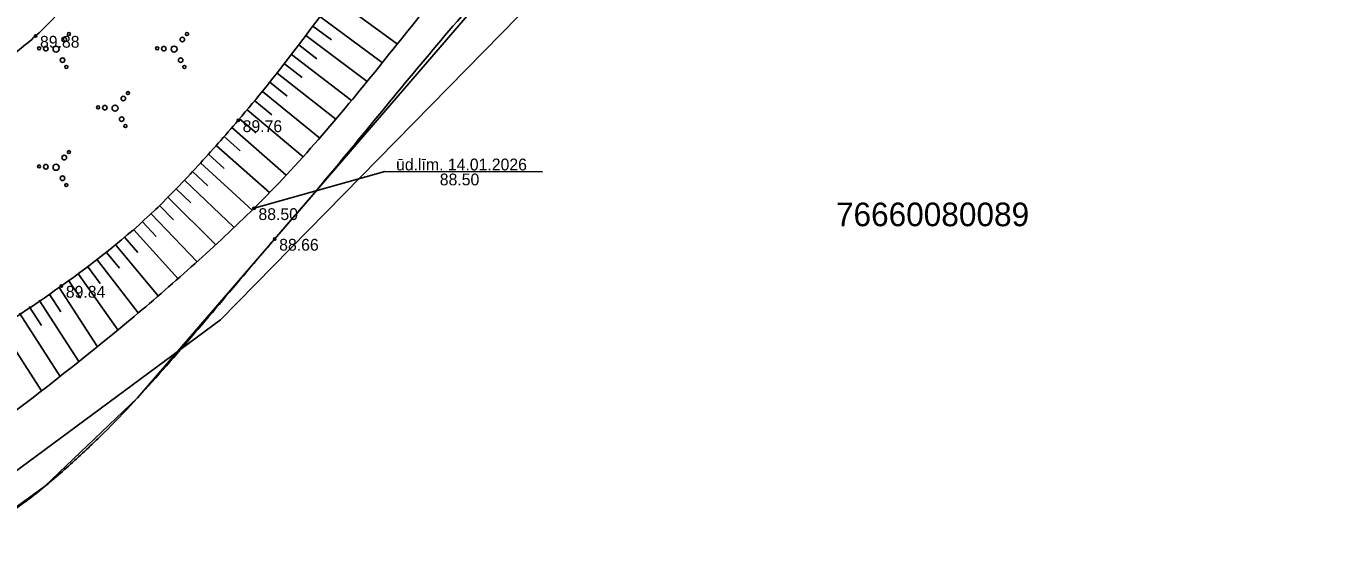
# Model space of a CAD drawing. Extents: x 635228 to 635525, y 248590 to 248800.
# Drawn here: x 635431.2 to 635486.1, y 248671.4 to 248693.5 of the extents above; entities that cross this region are included whole.
import ezdxf

# ---------------------------------------------------------------- set-up
doc = ezdxf.new("R2010")
doc.units = 0
for name, color, linetype in [('HIDG_GRAV_####_####_#', 7, 'Continuous'), ('HIDG_GRAV_####_TKST_#', 7, 'Continuous'), ('HIDG_PLIN_####_####_#', 7, 'Continuous'), ('RAMI_UZMR_####_####_#', 7, 'Continuous'), ('RELJ_AATZ_####_TKST_#', 7, 'Continuous'), ('RELJ_ELEM_####_####_#', 7, 'Continuous'), ('RELJ_HORZ_RESN_####_#', 7, 'Continuous'), ('RELJ_NOGA_####_####_#', 7, 'Continuous'), ('ROBZ_IERR_####_####_#', 7, 'Continuous'), ('ROBZ_IERR_####_TKST_#', 7, 'Continuous'), ('ROBZ_UZMR_####_####_#', 7, 'Continuous'), ('TERT_ELEM_####_####_#', 7, 'Continuous'), ('TERT_KONT_####_####_#', 7, 'Continuous')]:
    doc.layers.add(name, color=color, linetype=linetype)

msp = doc.modelspace()

# ---------------------------------------------------------------- linework, layer by layer
at = {"layer": 'HIDG_GRAV_####_####_#'}
for points in [[(635394.244, 248623.295), (635394.9074355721, 248630.6631552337), (635396.5650242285, 248636.944974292), (635397.8888882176, 248639.97580624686), (635399.2686043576, 248642.98780740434), (635400.0423829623, 248644.69884236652), (635400.835233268, 248646.3905777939), (635402.4795660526, 248649.72803076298), (635404.20443685, 248653.0239277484), (635406.0126797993, 248656.30203018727), (635407.0670223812, 248658.14081276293), (635408.1930324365, 248659.92698593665), (635409.4621962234, 248661.60192368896), (635410.172800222, 248662.37935865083), (635410.946, 248663.10700000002), (635413.0008032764, 248664.6744257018), (635415.1640977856, 248666.05372522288), (635417.3478434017, 248667.38916213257), (635419.464, 248668.825), (635422.2083511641, 248670.85354035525), (635424.965867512, 248672.86854694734), (635430.4558647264, 248676.93578902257), (635435.8049295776, 248681.1823865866), (635438.3862804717, 248683.4215875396), (635439.6466024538, 248684.57867623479), (635440.8840000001, 248685.76400000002), (635443.6087249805, 248688.6747140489), (635446.1599310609, 248691.73220612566), (635448.6719216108, 248694.81834513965), (635451.279, 248697.815), (635453.9336502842, 248700.48189136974), (635456.6811388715, 248703.07136968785), (635459.3523080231, 248705.7266631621), (635461.7780000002, 248708.59100000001), (635461.778, 248708.59100000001)], [(635396.7397638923, 248625.2320466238), (635397.9986579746, 248634.27312358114), (635398.9188026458, 248636.96227546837), (635399.5920874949, 248638.24717771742), (635399.9292604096, 248638.88899780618), (635400.2466831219, 248639.53584001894), (635401.591165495, 248642.41958219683), (635402.9524948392, 248645.2868638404), (635405.8217854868, 248650.96088254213), (635407.5583128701, 248653.91205967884), (635409.4799859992, 248656.7354955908), (635411.5283407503, 248659.48290512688), (635413.6449129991, 248662.20600313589), (635414.8182615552, 248663.6538935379), (635415.4704678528, 248664.3057478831), (635416.2076616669, 248664.85985159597), (635417.1601741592, 248665.41138033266), (635418.1313630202, 248665.91742947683), (635419.1067857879, 248666.41122678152), (635420.072, 248666.926), (635421.5645353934, 248667.7418115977), (635423.0692260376, 248668.5354410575), (635426.0762392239, 248670.12612318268), (635429.0153718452, 248671.8379856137), (635430.4352117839, 248672.78309045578), (635431.128452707, 248673.2855892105), (635431.8089561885, 248673.81096758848), (635433.1953696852, 248675.0040709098), (635434.526751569, 248676.2563297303), (635437.0226234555, 248678.92292892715), (635441.762, 248684.467), (635443.1273679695, 248686.0473501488), (635444.4678763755, 248687.6485508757), (635447.1219662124, 248690.87245996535), (635449.819572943, 248694.05663907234), (635451.2144774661, 248695.60817732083), (635452.6560000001, 248697.119), (635458.0231966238, 248702.2419696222), (635463.584, 248707.15000000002)]]:
    msp.add_spline(points, degree=3, dxfattribs=at)
at = {"layer": 'HIDG_PLIN_####_####_#'}
msp.add_lwpolyline([(635440.8840000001, 248685.76400000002), (635446.4215187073, 248687.31237986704), (635453.0919673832, 248687.30254225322)], dxfattribs=at)
at = {"layer": 'RAMI_UZMR_####_####_#'}
msp.add_lwpolyline([(635426.003, 248728.15499999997), (635436.69, 248722.584), (635450.108, 248715.45700000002), (635458.287, 248711.34600000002), (635461.7780000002, 248708.59100000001), (635463.584, 248707.15000000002), (635452.6560000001, 248697.119), (635441.762, 248684.467), (635435.9528772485, 248677.73413872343), (635432.018527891, 248673.97985762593), (635429.363741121, 248672.06248825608), (635427.0556775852, 248670.66460585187), (635420.072, 248666.926), (635415.05332695, 248664.00973325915), (635408.095218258, 248654.65947737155), (635398.6701763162, 248636.43948679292), (635398.046283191, 248634.41686083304), (635396.3166782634, 248622.87374513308), (635394.244, 248623.295), (635390.206, 248622.483), (635381.566, 248626.41900000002), (635379.918, 248627.738), (635364.657, 248634.36500000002)], dxfattribs=at)
at = {"layer": 'RELJ_ELEM_####_####_#'}
for centre in [(635431.635, 248693.06), (635440.2150000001, 248689.48700000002), (635440.8840000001, 248685.76400000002), (635441.762, 248684.467), (635432.728, 248682.47600000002)]:
    msp.add_circle(centre, 0.05, dxfattribs=at)
at = {"layer": 'RELJ_HORZ_RESN_####_#'}
msp.add_spline([(635396.8403365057, 248673.83023932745), (635398.5699520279, 248674.74721849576), (635400.1196081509, 248675.6687893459), (635401.3847631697, 248676.59316814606), (635401.8779834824, 248677.05585311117), (635402.2608753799, 248677.51857116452), (635402.5005008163, 248677.92779942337), (635402.9962003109, 248679.47940420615), (635403.1093939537, 248680.10527297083), (635403.2077718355, 248680.73304831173), (635403.3050539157, 248681.36081107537), (635403.4149601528, 248681.98664210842), (635403.9947087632, 248684.49620174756), (635404.4941894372, 248685.58182624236), (635404.822447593, 248686.0525951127), (635405.213, 248686.464), (635405.5227683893, 248686.49325254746), (635405.8948771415, 248686.27621660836), (635406.269797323, 248686.04907236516), (635406.588, 248686.048), (635407.1331532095, 248686.47133617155), (635407.6549224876, 248686.94769115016), (635408.6437981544, 248688.02779111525), (635410.511320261, 248690.47588617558), (635412.43838879, 248692.8856225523), (635414.0718482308, 248694.36296271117), (635414.672826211, 248694.7503376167), (635415.8418707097, 248695.38166460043), (635417.0157559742, 248695.99905223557), (635418.2014500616, 248696.5900310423), (635419.4059210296, 248697.14213154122), (635424.3998390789, 248699.29274669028), (635429.4588912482, 248701.50672660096), (635434.3873884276, 248704.0886148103), (635435.2434356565, 248704.60530447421), (635437.7315604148, 248706.27775516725), (635439.1970704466, 248707.5552960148), (635439.8338858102, 248708.26101524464), (635440.1227716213, 248708.63326282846), (635440.3898668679, 248709.01944554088), (635440.6922176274, 248709.6864690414), (635440.8034457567, 248710.32396866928)], degree=3, dxfattribs=at)
at = {"layer": 'RELJ_NOGA_####_####_#'}
for p, q in [((635444.2640867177, 248694.6815334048), (635446.9501521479, 248692.7079483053)), ((635443.6711792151, 248693.87626334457), (635446.3164226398, 248691.9252376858)), ((635443.3733437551, 248693.47464939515), (635444.159231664, 248692.8902927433)), ((635443.0742304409, 248693.0739865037), (635445.6670526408, 248691.12700530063)), ((635442.4707656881, 248692.2766022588), (635445.0102797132, 248690.3282610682)), ((635442.7734409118, 248692.67458055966), (635443.544555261, 248692.09194530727)), ((635442.165886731, 248691.8803093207), (635442.9197012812, 248691.29521855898)), ((635441.8583686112, 248691.48606120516), (635444.3460306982, 248689.53457838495)), ((635441.2345494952, 248690.70450682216), (635443.6628559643, 248688.73703135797)), ((635441.5480193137, 248691.09403852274), (635442.2846619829, 248690.50547088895)), ((635440.9176730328, 248690.31774175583), (635441.6351733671, 248689.7223950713)), ((635440.2724968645, 248689.55373259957), (635440.9714260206, 248688.95153464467)), ((635440.5970389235, 248689.93408666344), (635442.958460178, 248687.93922568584)), ((635439.944876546, 248689.1760233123), (635442.2476320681, 248687.16290094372)), ((635439.2844241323, 248688.42516061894), (635441.5428443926, 248686.42444521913)), ((635439.6155479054, 248688.799802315), (635440.3001597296, 248688.1974505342)), ((635438.9510520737, 248688.0525187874), (635439.6168422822, 248687.45103894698)), ((635438.276153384, 248687.31462318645), (635438.9206995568, 248686.71560371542)), ((635438.6150448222, 248687.68225136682), (635440.8048401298, 248685.6867319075)), ((635437.9339912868, 248686.95003711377), (635440.0377400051, 248684.94792143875)), ((635437.2383815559, 248686.231644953), (635439.2625636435, 248684.2212014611)), ((635437.5881101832, 248686.58897799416), (635438.2072488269, 248685.98740303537)), ((635436.8842699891, 248685.87865579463), (635437.4801655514, 248685.27329917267)), ((635436.1619816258, 248685.18711517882), (635436.7333918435, 248684.57161787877)), ((635436.5255786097, 248685.5303229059), (635438.4722431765, 248683.49912884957)), ((635435.7932493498, 248684.84943055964), (635437.6667843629, 248682.7811903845)), ((635435.0390315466, 248684.1928833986), (635436.829137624, 248682.05219983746)), ((635435.4189928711, 248684.5178794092), (635435.9683232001, 248683.88744733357)), ((635434.2609435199, 248683.5648307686), (635435.983178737, 248681.33217852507)), ((635434.6530570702, 248683.8750534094), (635435.1800791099, 248683.22053229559)), ((635433.4574724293, 248682.96962311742), (635435.1192793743, 248680.61247814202)), ((635433.8624592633, 248683.2628364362), (635434.3722396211, 248682.57773384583)), ((635432.6279048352, 248682.41137622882), (635434.2484871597, 248679.9012711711)), ((635433.0458890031, 248682.68574630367), (635433.537136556, 248681.95645475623)), ((635431.787682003, 248681.86913502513), (635433.4631615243, 248679.27084230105)), ((635432.2078449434, 248682.14017577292), (635432.7025924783, 248681.37386586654)), ((635430.9470252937, 248681.3275667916), (635432.6731329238, 248678.64622909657)), ((635431.3674439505, 248681.5982107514), (635431.8775093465, 248680.80587454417)), ((635430.1061815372, 248680.7862888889), (635431.879304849, 248678.02717532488))]:
    msp.add_line(p, q, dxfattribs=at)
msp.add_spline([(635390.206, 248622.483), (635392.6761559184, 248639.41621940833), (635395.6724652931, 248647.2597307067), (635397.9131924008, 248650.95381667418), (635399.048256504, 248652.79837067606), (635400.128, 248654.662), (635400.9493075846, 248656.2558432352), (635403.3016292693, 248661.16811378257), (635405.1862207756, 248664.14373210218), (635407.706, 248666.499), (635412.1610828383, 248669.3503906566), (635416.627, 248672.168), (635424.6828055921, 248677.31078055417), (635432.728, 248682.47600000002), (635436.7060689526, 248685.70428438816), (635438.5008534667, 248687.5575466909), (635440.2150000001, 248689.48700000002), (635442.5291182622, 248692.3528262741), (635444.7219287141, 248695.30565037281), (635446.9190248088, 248698.24939928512), (635449.246, 248701.08800000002), (635451.3600052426, 248703.48451832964), (635453.4937434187, 248705.86484004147), (635457.9500000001, 248710.44), (635458.6576193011, 248711.10744185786)], degree=3, dxfattribs=at)
at = {"layer": 'ROBZ_IERR_####_####_#'}
msp.add_lwpolyline([(635522.337313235, 248635.85405923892), (635430.9589999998, 248667.77300000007), (635424.5429999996, 248670.01400000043), (635439.4570000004, 248681.03800000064), (635465.4589999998, 248707.53900000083), (635482.5609999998, 248729.82799999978), (635498.1289999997, 248747.85500000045)], dxfattribs=at)
at = {"layer": 'ROBZ_UZMR_####_####_#'}
msp.add_lwpolyline([(635325.5420000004, 248659.74000000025), (635329.6529999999, 248676.3660000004), (635327.79, 248676.82799999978), (635337.4600999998, 248688.65990000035), (635343.3430000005, 248703.1199999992), (635360.483, 248762.61500000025), (635458.6069999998, 248711.13399999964), (635465.4589999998, 248707.53900000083), (635439.4570000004, 248681.03800000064), (635424.5429999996, 248670.01400000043), (635420.9790000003, 248667.37900000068), (635407.0700000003, 248653.17999999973), (635400.0669999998, 248641.1490000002), (635395.1619999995, 248617.53900000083), (635389.0310000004, 248621.06200000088), (635375.858, 248629.11500000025)], close=True, dxfattribs=at)
at = {"layer": 'TERT_ELEM_####_####_#'}
for centre, radius in [((635432.8475200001, 248692.90767999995), 0.09600000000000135), ((635433.044, 248693.13935999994), 0.06400000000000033), ((635437.8475200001, 248692.90767999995), 0.09600000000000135), ((635438.044, 248693.13935999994), 0.06400000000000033), ((635431.7816, 248692.53423999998), 0.06400000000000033), ((635432.06608, 248692.52079999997), 0.09600000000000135), ((635432.5, 248692.5), 0.12800000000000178), ((635436.7816, 248692.53423999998), 0.06400000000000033), ((635437.06608, 248692.52079999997), 0.09600000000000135), ((635437.5, 248692.5), 0.12800000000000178), ((635432.77648, 248692.03311999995), 0.09600000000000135), ((635432.93392, 248691.74383999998), 0.06400000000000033), ((635437.77648, 248692.03311999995), 0.09600000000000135), ((635437.93392, 248691.74383999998), 0.06400000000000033), ((635435.544, 248690.63935999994), 0.06400000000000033), ((635434.2816, 248690.03423999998), 0.06400000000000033), ((635434.56608, 248690.02079999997), 0.09600000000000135), ((635435, 248690), 0.12800000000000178), ((635435.3475200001, 248690.40767999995), 0.09600000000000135), ((635435.27648, 248689.53311999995), 0.09600000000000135), ((635435.43392, 248689.24383999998), 0.06400000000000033), ((635432.8475200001, 248687.90767999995), 0.09600000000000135), ((635433.044, 248688.13935999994), 0.06400000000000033), ((635431.7816, 248687.53423999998), 0.06400000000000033), ((635432.06608, 248687.52079999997), 0.09600000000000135), ((635432.5, 248687.5), 0.12800000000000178), ((635432.77648, 248687.03311999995), 0.09600000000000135), ((635432.93392, 248686.74383999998), 0.06400000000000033)]:
    msp.add_circle(centre, radius, dxfattribs=at)
at = {"layer": 'TERT_KONT_####_####_#'}
msp.add_spline([(635381.566, 248626.41900000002), (635384.141, 248634.765), (635385.389202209, 248637.7914590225), (635387.0292419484, 248640.6516206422), (635388.8146607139, 248643.4497219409), (635389.6848689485, 248644.8580740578), (635390.4990000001, 248646.29), (635392.0226550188, 248649.21918285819), (635393.5071185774, 248652.1702394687), (635395.0017728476, 248655.12192634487), (635396.556, 248658.053), (635399.9011134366, 248663.08488427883), (635403.9259848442, 248667.61643358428), (635408.395257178, 248671.78623589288), (635410.7229946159, 248673.7787906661), (635413.0735733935, 248675.7328791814), (635414.4692599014, 248676.62068389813), (635415.9938205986, 248677.30794837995), (635417.5018643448, 248678.0054584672), (635418.848, 248678.924), (635420.219040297, 248680.28079949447), (635421.4913245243, 248681.74225536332), (635423.8682567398, 248684.84208090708), (635426.2360605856, 248687.94936599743), (635428.1606833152, 248690.11983046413), (635428.8520000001, 248690.79), (635429.5317929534, 248691.3720486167), (635430.2428233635, 248691.92597447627), (635430.954192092, 248692.47941309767), (635431.635, 248693.06), (635432.7520114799, 248694.18745503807), (635433.7815998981, 248695.39485218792), (635435.7079899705, 248697.94525714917), (635437.6731350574, 248700.50278353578), (635438.7511672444, 248701.71908246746), (635439.936, 248702.85900000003), (635442.1191491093, 248704.47891720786), (635444.4652000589, 248705.76616705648), (635446.9243060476, 248706.83607415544), (635448.1806775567, 248707.32556311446), (635449.4466202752, 248707.80396311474), (635450.5789798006, 248708.1275799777), (635451.7602437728, 248708.30057270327), (635452.9245409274, 248708.35276985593), (635454.0060000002, 248708.314), (635454.3355621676, 248708.1390314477), (635454.6423695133, 248707.79518323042), (635454.9454921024, 248707.47799339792), (635455.2640000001, 248707.383), (635455.8819855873, 248707.57371461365), (635456.5298319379, 248707.8540188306), (635457.157262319, 248708.21606363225), (635457.714, 248708.652), (635459.5420464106, 248710.35555231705)], degree=3, dxfattribs=at)

# ---------------------------------------------------------------- texts
at = {"layer": 'HIDG_GRAV_####_TKST_#'}
for s, p in [('ūd.līm. 14.01.2026', (635446.8968134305, 248687.36468236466)), ('88.50', (635448.7462974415, 248686.73288597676))]:
    msp.add_text(s, height=0.5, dxfattribs=at).set_placement(p)
at = {"layer": 'RELJ_AATZ_####_TKST_#'}
for s, p in [(' 89.88', (635431.635, 248692.56)), (' 89.76', (635440.2150000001, 248688.98700000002)), (' 88.50', (635440.8840000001, 248685.26400000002)), (' 88.66', (635441.762, 248683.967)), (' 89.84', (635432.728, 248681.97600000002))]:
    msp.add_text(s, height=0.5, dxfattribs=at).set_placement(p)
at = {"layer": 'ROBZ_IERR_####_TKST_#'}
msp.add_text('76660080089', height=1, dxfattribs=at).set_placement((635465.5195457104, 248685.0022917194))

doc.saveas('drawing.dxf')
